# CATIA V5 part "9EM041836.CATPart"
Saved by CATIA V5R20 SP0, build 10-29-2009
Part number: 9EM041836
Revision: ANY
Definition: UNKNOWN
Nomenclature: 9EM041836
Source: Unknown
Bounding box of the stored display mesh (mm): x -9 to 9, y -9 to 9, z 0 to 36
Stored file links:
  C:\Users\Utente\Desktop\IO LAVORO\3D X SITO CF\X SITO\3D files UM\UM043642 PRODUCT\9EM041836.CATPart
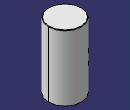
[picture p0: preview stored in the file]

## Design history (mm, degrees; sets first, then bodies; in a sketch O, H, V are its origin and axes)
Body1 "Taladro de diámetro de Ø3.5 (3.5)7" (main body)
  Solid1: solid without history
